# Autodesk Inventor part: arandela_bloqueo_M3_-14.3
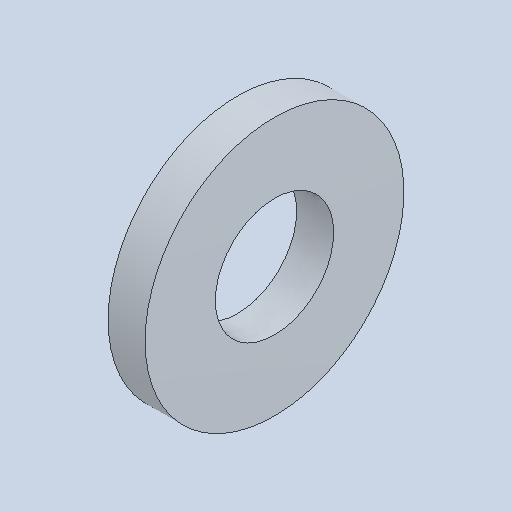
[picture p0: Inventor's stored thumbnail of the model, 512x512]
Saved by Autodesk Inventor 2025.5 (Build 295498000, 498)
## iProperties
Created: 2026-10
Part Number: arandela_bloqueo_M3_-14.3
Material: Genérico
Document SubType Name: Modeling
Designer: Luis M
Density: 1 g/cm^3
Appearance: Valor por defecto
Author: Luis M
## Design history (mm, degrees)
feature "Base1"
node "Sólido1"
